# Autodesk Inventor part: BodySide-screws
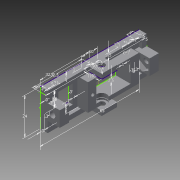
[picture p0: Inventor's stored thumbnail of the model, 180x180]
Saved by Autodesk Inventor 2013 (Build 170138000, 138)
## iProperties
Created: 2013-03
Part Number: BodySide-screws
Material: Generic
Document SubType Name: Modeling
Designer: frankenteddy
Density: 1 g/cm^3
Author: frankenteddy
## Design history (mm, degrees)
node "Blocks"
  sketch "Block1"
    geometry: L1 (49.279, 30.472)-(71.779, 30.472); L2 (71.779, 30.472)-(71.779, 18.072); L3 (71.779, 18.072)-(49.279, 18.072); L4 (49.279, 18.072)-(49.279, 30.472); L5 (49.279, 30.472)-(44.779, 30.472); L6 (44.779, 30.472)-(44.779, 18.072); L7 (44.779, 18.072)-(49.279, 18.072); L8 (49.279, 18.072)-(49.279, 30.472); L9 (71.779, 30.472)-(76.279, 30.472); L10 (76.279, 30.472)-(76.279, 18.072); L11 (76.279, 18.072)-(71.779, 18.072); L12 (71.779, 18.072)-(71.779, 30.472); L13 (44.779, 24.272)-(76.279, 24.272); L14 (60.529, 30.472)-(60.529, 18.072); L15 (47.029, 30.472)-(47.029, 18.072); L16 (74.029, 30.472)-(74.029, 18.072); C1 r 1.1 at (47.029, 24.272); C2 r 1.1 at (74.029, 24.272); 1 further point
    constraints: 32 end point, 8 midpoint, 6 parallel, 3 horizontal, 3 perpendicular, 2 centre point, 2 point on line
    dimensions: "d17" = 22.5 distance of L2.end L3.end; "d18" = 12.4 distance of L1.end L2.end; "d19" = 4.5 distance of L7.end L6.end; "d20" = 4.5 distance of L10.end L11.end; "d21" = 2.2 diameter of C1; "d22" = 2.2 diameter of C2; "d23" = 2.25 distance between parallel lines of L10 L16
sketch "Sketch1"
  geometry: L1 (30, 12)-(-35, 12); L2 (-35, 12)-(-35, -12); L3 (-35, -12)-(30, -12); L4 (30, -12)-(30, 12); L5 (30, 5)-(27, 5); L6 (27, 5)-(27, -5); L7 (27, -5)-(30, -5); L8 (30, -5)-(30, 5); L9 (2.5, 12)-(-7.5, 12); L10 (-7.5, 12)-(-7.5, 9); L11 (-7.5, 9)-(2.5, 9); L12 (2.5, 9)-(2.5, 12); L13 (20, 8.7)-(-13.5, 8.7); L14 (-13.5, 8.7)-(-13.5, -8.7); L15 (-13.5, -8.7)-(20, -8.7); L16 (20, -8.7)-(20, 8.7); L17 (-35, 5)-(-32, 5); L18 (-32, 5)-(-32, -5); L19 (-32, -5)-(-35, -5); L20 (-35, -5)-(-35, 5); L21 (-32, 5)-(-29, 5); L22 (-29, 5)-(-29, -5); L23 (-29, -5)-(-32, -5); L24 (-32, -5)-(-32, 5); L25 (-16.5, 6)-(-26, 6); L26 (-26, 6)-(-26, -6); L27 (-26, -6)-(-16.5, -6); L28 (-16.5, -6)-(-16.5, 6); L29 (-36.862, 9)-(-31.424, 9); L30 (27, 5)-(24, 5); L31 (24, 5)-(24, -5); L32 (24, -5)-(27, -5); L33 (27, -5)-(27, 5); L34 (-2.5, 9)-(-2.5, 12); 9 further points
  constraints: 68 end point, 16 parallel, 9 perpendicular, 8 horizontal, 6 midpoint, 5 point on line, 4 horizontal alignment, 1 coincident, 1 other
  dimensions: "d4" = 3 distance of L7.end L6.end; "d13" = 10 distance of L11.end L10.end; "d14" = 3 distance of L10.end L9.end; "d24" = 11 dimension on L4; "d29" = 2.5 dimension on L13; "d30" = 2.5 dimension on L15; "d31" = 1 dimension on L14; "d36" = 3 distance of L18.end L19.end; "d37" = 10 distance of L17.end L18.end; "d44" = 3 distance of L22.end L23.end; "d45" = 10 distance of L21.end L22.end; "d56" = 6 distance between parallel lines of L25 L1; "d57" = 6 distance between parallel lines of L27 L3; "d58" = 3 distance between parallel lines of L22 L26; "d59" = 3 distance between parallel lines of L14 L28; "d64" = 24 distance between parallel lines of L3 L1; "d65" = 65 distance of L2.end L3.end; "d66" = 3.3 distance between parallel lines of L1 L13; "d68" = 0 distance between parallel lines of L18 L24; "d72" = 1 dimension on L16; "d89" = 3 distance between parallel lines of L29 L1; "d104" = 3 distance of L32.end L31.end; "d105" = 4 distance between parallel lines of L16 L31 (derived); "d146" = 32.5 distance between parallel lines of L2 L34
  node "Block1:1" dims "d4" = 3, "d13" = 10, "d14" = 3, "d24" = 11, "d29" = 2.5, "d30" = 2.5, "d31" = 1, "d36" = 3, "d37" = 10, "d44" = 3, "d45" = 10, "d56" = 6, "d57" = 6, "d58" = 3, "d59" = 3, "d64" = 24, "d65" = 65, "d66" = 3.3, "d68" = 0, "d72" = 1, "d89" = 3, "d104" = 3, "d105" = 4 (derived), "d146" = 32.5
extrude "Extrusion18" new body sketch "Sketch1" distance "d106" = 3; taper "d107" = 0 deg
extrude "Extrusion19" join sketch "Sketch1" distance "d108" = 13; taper "d109" = 0 deg
extrude "Extrusion20" join sketch "Sketch1" distance "d110" = 13; taper "d111" = 0 deg
extrude "Extrusion21" join sketch "Sketch1" distance "d112" = 13; taper "d113" = 0 deg
sketch "Sketch11"
  geometry: L1 (13, 37.5)-(3, 37.5); L2 (3, 37.5)-(3, 27.5); L3 (3, 27.5)-(13, 27.5); L4 (13, 27.5)-(13, 37.5); L5 (8, 37.5)-(8, 27.5); L6 (13, 32.5)-(3, 32.5); C1 r 2 at (8, 32.5); 1 further point
  constraints: 12 end point, 5 midpoint, 2 parallel, 1 centre point, 1 horizontal, 1 perpendicular
  dimensions: "d114" = 10 distance of L3.end L2.end (derived); "d115" = 10 distance of L2.end L1.end (derived); "d116" = 4 diameter of C1
extrude "Extrusion22" cut sketch "Sketch11" distance "d117" = 3; taper "d118" = 0 deg
sketch "Sketch12"
  geometry: L1 (13, -7)-(3, -7); L2 (3, -7)-(3, -17); L3 (3, -17)-(13, -17); L4 (13, -17)-(13, -7); L5 (8, -7)-(8, -17); L6 (13, -12)-(3, -12); C1 r 2 at (8, -12); 1 further point
  constraints: 12 end point, 5 midpoint, 2 parallel, 1 centre point, 1 horizontal, 1 perpendicular
  dimensions: "d119" = 10 distance of L3.end L2.end (derived); "d120" = 10 distance of L2.end L1.end (derived); "d121" = 4 diameter of C1
extrude "Extrusion23" cut sketch "Sketch12" distance "d122" = 6; taper "d123" = 0 deg
sketch "Sketch13"
  geometry: L1 (13, 17)-(3, 17); L2 (3, 17)-(3, 7); L3 (3, 7)-(13, 7); L4 (13, 7)-(13, 17); L5 (8, 17)-(8, 7); L6 (13, 12)-(3, 12); C1 r 2 at (8, 12); 1 further point
  constraints: 12 end point, 5 midpoint, 2 parallel, 1 centre point, 1 horizontal, 1 perpendicular
  dimensions: "d124" = 10 distance of L3.end L2.end (derived); "d125" = 10 distance of L2.end L1.end (derived); "d126" = 4 diameter of C1
extrude "Extrusion24" cut sketch "Sketch13" distance "d127" = 6; taper "d128" = 0 deg
sketch "Sketch14"
  geometry: L1 (0, 10)-(10, 10); L2 (10, 10)-(10, 0); L3 (10, 0)-(0, 0); L4 (0, 0)-(0, 10); L5 (5, 10)-(5, 0); L6 (10, 5)-(0, 5); L7 (5, 9.879)-(9.225, 7.439); L8 (9.225, 7.439)-(9.225, 2.561); L9 (9.225, 2.561)-(5, 0.121); L10 (5, 0.121)-(0.775, 2.561); L11 (0.775, 2.561)-(0.775, 7.439); L12 (0.775, 7.439)-(5, 9.879); C1 r 2 at (5, 5) reference; 2 further points
  constraints: 24 end point, 4 midpoint, 2 parallel, 1 coincident, 1 horizontal, 1 perpendicular, 1 point on line, 13 other
  dimensions: "d129" = 10 distance of L2.end L3.end (derived); "d130" = 10 distance of L1.end L2.end (derived); "d131" = 8.45 distance between parallel lines of L8 L11
extrude "Extrusion25" cut sketch "Sketch14" distance "d132" = 3; taper "d133" = 0 deg
sketch "Sketch15"
  geometry: L1 (0, 10)-(10, 10); L2 (10, 10)-(10, 0); L3 (10, 0)-(0, 0); L4 (0, 0)-(0, 10); L5 (5, 10)-(5, 0); L6 (10, 5)-(0, 5); L7 (5, 9.879)-(9.225, 7.439); L8 (9.225, 7.439)-(9.225, 2.561); L9 (9.225, 2.561)-(5, 0.121); L10 (5, 0.121)-(0.775, 2.561); L11 (0.775, 2.561)-(0.775, 7.439); L12 (0.775, 7.439)-(5, 9.879); C1 r 2 at (5, 5) reference; 2 further points
  constraints: 24 end point, 4 midpoint, 2 parallel, 1 coincident, 1 horizontal, 1 perpendicular, 1 point on line, 13 other
  dimensions: "d134" = 10 distance of L2.end L3.end (derived); "d135" = 10 distance of L1.end L2.end (derived); "d136" = 8.45 distance between parallel lines of L8 L11
extrude "Extrusion26" cut sketch "Sketch15" distance "d137" = 3; taper "d138" = 0 deg
extrude "Extrusion27" join sketch "Sketch1" distance "d139" = 10; taper "d140" = 0 deg
sketch "Sketch16"
  geometry: L1 (0, 0)-(10, 0); L2 (10, 0)-(10, -10); L3 (10, -10)-(0, -10); L4 (0, -10)-(0, 0); L5 (0, -5)-(10, -5); L6 (5, 0)-(5, -10); C1 r 2 at (5, -5) reference; C2 r 3.3 at (5, -5); 1 further point
  constraints: 12 end point, 4 midpoint, 2 parallel, 1 centre point, 1 coincident, 1 horizontal, 1 perpendicular
  dimensions: "d141" = 10 distance of L2.end L3.end (derived); "d142" = 10 distance of L1.end L2.end (derived); "d143" = 6.6 diameter of C2
extrude "Extrusion28" cut sketch "Sketch16" distance "d144" = 4; taper "d145" = 0 deg
mirror "Mirror4"
workplane "Work Plane5"
sketch "Sketch17"
  geometry: L1 (0, 0)-(3, 0); L2 (3, 0)-(3, 65); L3 (3, 65)-(0, 65); L4 (0, 65)-(0, 0); L5 (0, 61)-(3, 61); L6 (3.5, 61)-(-1.5, 61); L7 (0, 4)-(3, 4); L8 (3.5, 4)-(-1.5, 4); L9 (0, 32.5)-(3, 32.5); L10 (3.5, 32.5)-(-1.5, 32.5); A1 r 2.5 centre (1, 61) between (3.5, 61) and (-1.5, 61); A2 r 2.5 centre (1, 4) between (3.5, 4) and (-1.5, 4); A3 r 2.5 centre (1, 32.5) between (3.5, 32.5) and (-1.5, 32.5); 1 further point
  constraints: 20 end point, 7 point on line, 6 point on circle, 4 perpendicular, 3 centre point, 2 collinear, 2 midpoint, 2 parallel, 1 horizontal
  dimensions: "d147" = 3 distance of L3.end L2.end; "d148" = 65 distance of L2.end L1.end; "d151" = 5 diameter of A1; "d152" = 1 distance from line of L4 A1.centre; "d153" = 4 distance between parallel lines of L5 L3; "d154" = 4 distance between parallel lines of L7 L1; "d155" = 5 diameter of A2; "d156" = 1 distance from line of A2.centre L4; "d163" = 32.5 distance between parallel lines of L1 L9; "d164" = 5 diameter of A3; "d165" = 1 distance from line of L4 A3.centre
sketch "Sketch18"
  geometry: L1 (-9, -7.5)-(-12, -7.5) reference; L2 (-12, -7.5)-(-12, -35) reference; L3 (-5, -35)-(-12, -35); L4 (-12, -35)-(-12, -32); L5 (-12, -32)-(-5, -32); L6 (-5, -32)-(-5, -35); L7 (-12, -32)-(-9, -32); L8 (-9, -32)-(-9, -7.5); L9 (-9, -7.5)-(-12, -7.5); L10 (-12, -7.5)-(-12, -32); 1 further point
  constraints: 16 end point, 4 parallel, 2 horizontal, 2 perpendicular, 1 point on line
  dimensions: "d166" = 3 distance of L3.end L4.end
extrude "Extrusion29" join sketch "Sketch18" distance "d167" = 2; taper "d168" = 0 deg
sketch "Sketch19"
  geometry: L1 (-5, 30)-(-12, 30) reference; L2 (-12, 30)-(-12, 2.5) reference; L3 (-5, 30)-(-12, 30); L4 (-12, 30)-(-12, 27); L5 (-12, 27)-(-5, 27); L6 (-5, 27)-(-5, 30); L7 (-12, 27)-(-9, 27); L8 (-9, 27)-(-9, 2.5); L9 (-9, 2.5)-(-12, 2.5); L10 (-12, 2.5)-(-12, 27); 1 further point
  constraints: 16 end point, 4 parallel, 2 horizontal, 2 perpendicular, 1 point on line
  dimensions: "d169" = 3 distance of L4.end L3.end
extrude "Extrusion30" join sketch "Sketch19" distance "d170" = 2; taper "d171" = 0 deg
mirror "Mirror6"
extrude "Extrusion31" cut sketch "Sketch16" distance "d172" = 1; taper "d173" = 0 deg
mirror "Mirror7"
body "Solid2"
